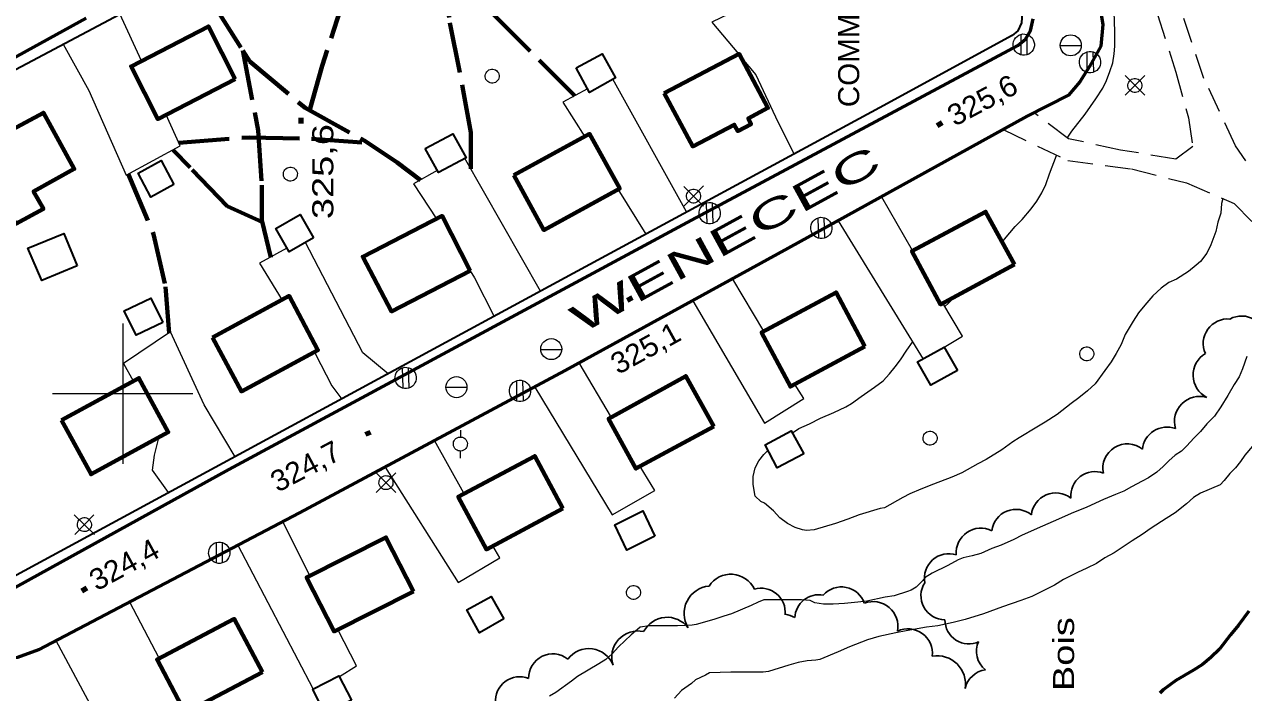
# Model space of a CAD drawing. Extents: x 240591 to 242335, y 5323482 to 5326937.
# Drawn here: x 241186 to 241359.7, y 5324557.4 to 5324652.6 of the extents above; entities that cross this region are included whole.
import ezdxf
from ezdxf.enums import TextEntityAlignment as Align

# ---------------------------------------------------------------- set-up
doc = ezdxf.new("R2010")
doc.units = 0
doc.header["$LTSCALE"] = 1.2
doc.linetypes.add('LONG_DASHED', pattern=[7.5, 6, -1.5])
doc.linetypes.add('MEDIUM_DASHED', pattern=[4.5, 3, -1.5])
for name, color, linetype, lineweight in [('1', 7, 'Continuous', 53), ('19', 7, 'Continuous', 13), ('2', 7, 'Continuous', 13), ('21', 7, 'Continuous', 53), ('22', 7, 'LONG_DASHED', 70), ('3', 7, 'Continuous', 140), ('31', 7, 'Continuous', 70), ('36', 7, 'Continuous', 13), ('44', 7, 'Continuous', 25), ('61', 7, 'Continuous', 13)]:
    doc.layers.add(name, color=color, linetype=linetype, lineweight=lineweight)

msp = doc.modelspace()

# ---------------------------------------------------------------- linework, layer by layer
at = {"layer": '1', "linetype": 'LONG_DASHED'}
msp.add_lwpolyline([(241360.4, 5324569), (241358.9, 5324567), (241357.8, 5324565.6), (241356.2, 5324563.6), (241355, 5324562.4), (241353.8, 5324561.4), (241352.5, 5324560.6), (241350, 5324559.1), (241348.2, 5324557.8), (241347.7, 5324557.3)], dxfattribs=at)
at = {"layer": '19'}
for p, q in [((241202.7, 5324647.4), (241199.6, 5324654.1)), ((241280.3, 5324625.9), (241269.8, 5324644.8)), ((241259.5, 5324614.6), (241248.7, 5324633.6)), ((241270.5, 5324629.1), (241274.5, 5324622.7)), ((241312.5, 5324620.4), (241308.1, 5324628)), ((241301.9, 5324624.6), (241314, 5324604.9)), ((241291.3, 5324608.9), (241286.9, 5324616.3)), ((241269.6, 5324596.6), (241265, 5324604.4)), ((241248.6, 5324585.8), (241244.4, 5324593.3)), ((241226.7, 5324574), (241222.8, 5324581.7)), ((241216.4, 5324578.4), (241227.1, 5324558)), ((241205.2, 5324562.3), (241201, 5324570.3))]:
    msp.add_line(p, q, dxfattribs=at)
at = {"layer": '19', "linetype": 'MEDIUM_DASHED'}
for points in [[(241392.5, 5324606.1), (241384.7, 5324607.7), (241378.2, 5324613), (241369.4, 5324621), (241363, 5324628.7), (241358.5, 5324635.3), (241354, 5324644.9), (241349.9, 5324657.2), (241346.1, 5324667.4), (241343.3, 5324672.7), (241341.3, 5324676.6)], [(241335.8, 5324674.5), (241340.6, 5324670.9), (241344.5, 5324664.1), (241347.4, 5324654), (241350, 5324645.8), (241351.8, 5324639.3), (241352.4, 5324635.2), (241350, 5324633.4), (241342.1, 5324634.7), (241334.7, 5324636.3), (241329.8, 5324640)], [(241325.4, 5324637.6), (241334.6, 5324633.2), (241343.7, 5324632), (241351.5, 5324630), (241358.3, 5324627.1), (241363.6, 5324621.6), (241368.5, 5324615.9), (241373.3, 5324610.3), (241377.7, 5324604.4), (241381.7, 5324599.7), (241386.5, 5324594.9)]]:
    msp.add_lwpolyline(points, dxfattribs=at)
at = {"layer": '19'}
for points in [[(241286.4, 5324654.1), (241283.9, 5324652.9), (241287.7, 5324648.4)], [(241191.5, 5324649.8), (241195.2, 5324643.2), (241200.5, 5324631.1), (241208.2, 5324635.3), (241206.2, 5324639.7)], [(241288.2, 5324647.8), (241290.2, 5324645.4), (241293.3, 5324638.7), (241295.6, 5324634.2)], [(241266.2, 5324643.4), (241262.7, 5324641.5), (241265.8, 5324636.6)], [(241244.8, 5324631.8), (241241.4, 5324629.9), (241244.7, 5324624.9)], [(241223.4, 5324620.7), (241219.5, 5324618.6), (241222.7, 5324613.3)], [(241237.8, 5324602.8), (241234.2, 5324605.8), (241226, 5324621.6)], [(241249.5, 5324617.5), (241250.1, 5324616.5), (241252.9, 5324611)], [(241281.2, 5324613.2), (241291.4, 5324595.8), (241297, 5324599.3), (241295.7, 5324601.4)], [(241317, 5324606.6), (241319.6, 5324608.2), (241316.8, 5324612.9)], [(241216, 5324591), (241211.6, 5324598.4), (241206.8, 5324608.8), (241200.1, 5324604.3), (241201.5, 5324601.8)], [(241227.3, 5324605.9), (241227.4, 5324605.7), (241229.8, 5324601.1), (241231.2, 5324599.2)], [(241258.7, 5324600.9), (241269.7, 5324582.7), (241275.8, 5324586.2), (241273.7, 5324589.6)], [(241205.1, 5324593.7), (241204.5, 5324591.2), (241204.2, 5324589.1), (241206.5, 5324585.9)], [(241237.4, 5324589.5), (241247.8, 5324573.1), (241253.7, 5324576.6), (241252.7, 5324578.3)], [(241230.9, 5324559.7), (241233.3, 5324561.2), (241230.7, 5324566.3)], [(241190.5, 5324564.8), (241202.3, 5324542.8), (241208.4, 5324546.8)]]:
    msp.add_lwpolyline(points, dxfattribs=at)
at = {"layer": '2'}
for points in [[(241337.1, 5324639.8), (241338.6, 5324642), (241339.6, 5324643.5), (241340.1, 5324644.6), (241340.6, 5324645.9), (241341, 5324647.1), (241341.2, 5324648.4), (241341.3, 5324649.5), (241341.3, 5324651.6), (241341.2, 5324654.4), (241341, 5324655.7), (241340.6, 5324658), (241340.1, 5324660.7), (241339.7, 5324662.3), (241339.3, 5324663.8), (241338.6, 5324666.3), (241338, 5324668.2), (241337.6, 5324670.1), (241337.3, 5324671.8), (241337.3, 5324673.4)], [(241334.5, 5324636.4), (241335.2, 5324637.4), (241337.1, 5324639.8)], [(241325.3, 5324621.6), (241325.6, 5324622), (241327.1, 5324623.8), (241328.1, 5324624.8), (241329.4, 5324626.3), (241330.2, 5324627.4), (241330.9, 5324628.6), (241331.5, 5324629.8), (241332, 5324631.3), (241333, 5324633.9)], [(241356.7, 5324627.8), (241356.5, 5324627.1), (241356.4, 5324625.7), (241356, 5324624.4), (241355.7, 5324623.1), (241355, 5324621.2), (241354.4, 5324620), (241353.5, 5324618.8), (241352.9, 5324618.3), (241351.8, 5324617.4), (241350.1, 5324616.3), (241349, 5324615.8), (241347.9, 5324615), (241346.7, 5324613.9), (241345.6, 5324612.6), (241344.7, 5324611.5), (241343.9, 5324610.3), (241342.8, 5324608.4), (241342.2, 5324607), (241341.5, 5324605.7), (241340.8, 5324604.5), (241339.9, 5324603.3), (241338.5, 5324601.4), (241337.4, 5324600.4), (241336.2, 5324599.4), (241335.1, 5324598.6), (241333.1, 5324597), (241331.4, 5324595.9), (241330.2, 5324595.2), (241327.7, 5324593.7), (241326.8, 5324593.1), (241325.2, 5324592), (241323, 5324590.6), (241321.8, 5324590), (241319.5, 5324588.7), (241318.1, 5324588.1), (241315.5, 5324587.1), (241313.7, 5324586.4), (241312.1, 5324585.7), (241311.1, 5324585.2), (241308.5, 5324583.7), (241307.9, 5324583.6), (241304.9, 5324582.7), (241303.3, 5324582.1), (241301.5, 5324581.5), (241298.5, 5324580.6), (241297.4, 5324580.5), (241296.8, 5324580.6), (241295.8, 5324580.9), (241294.7, 5324581.5), (241293.6, 5324582.3), (241292.7, 5324583.3), (241291.4, 5324584.4), (241290.9, 5324584.6), (241290.1, 5324585.4), (241290, 5324585.9), (241289.8, 5324587.1), (241289.8, 5324588.2), (241290.1, 5324589.4), (241290.6, 5324590.4), (241291.3, 5324591.3), (241291.9, 5324591.9)], [(241317.1, 5324612.4), (241317.6, 5324612.9), (241318.6, 5324613.9)], [(241374.6, 5324608.4), (241373.9, 5324607.5), (241373.1, 5324606.3), (241371.9, 5324604.4), (241371.3, 5324603.3), (241370.2, 5324601.3), (241368.8, 5324598.7), (241367.8, 5324597.5), (241367.3, 5324597.2), (241364.9, 5324595.7), (241362.5, 5324594), (241361.7, 5324593.3), (241360.9, 5324592.5), (241359.8, 5324591.2), (241359.2, 5324590.3), (241358.5, 5324589.4), (241357.7, 5324588.6), (241356.9, 5324587.6), (241356.3, 5324587)], [(241295.4, 5324594.4), (241296.3, 5324595), (241297.8, 5324595.7), (241299.4, 5324596.5), (241301.3, 5324597.3), (241303, 5324598.1), (241303.8, 5324598.6), (241305.2, 5324599.6), (241307.1, 5324600.9), (241308.3, 5324601.8), (241309.2, 5324602.8), (241310, 5324603.8), (241310.8, 5324604.8), (241311.7, 5324606.2), (241312.5, 5324607.3)], [(241360.1, 5324605.3), (241359.5, 5324603.5), (241359, 5324602.4), (241358.3, 5324601.3), (241357.4, 5324599.7), (241356.4, 5324598.1), (241355.5, 5324596.8), (241354.4, 5324595.7), (241353.5, 5324594.6), (241352.6, 5324593.7), (241351.5, 5324592.5), (241350.8, 5324591.8), (241349.9, 5324591.2), (241349, 5324590.4), (241348.2, 5324589.6), (241347.3, 5324588.8), (241346.1, 5324588), (241345.2, 5324587.5), (241343.7, 5324586.7), (241342.6, 5324586.1), (241341.4, 5324585.6), (241339.7, 5324584.9), (241337.3, 5324583.8), (241335.1, 5324582.9), (241333.3, 5324582.1)], [(241333.3, 5324582.1), (241331, 5324581.1), (241328.1, 5324579.8), (241326.9, 5324579.2), (241325.1, 5324578.4), (241323.8, 5324577.9), (241322.2, 5324577.2), (241321, 5324576.9), (241319.7, 5324576.6), (241319, 5324576.3), (241317.5, 5324575.5), (241315.3, 5324574.4), (241314.3, 5324573.8), (241313.9, 5324573.3), (241313, 5324572.4), (241312.3, 5324572), (241311.8, 5324571.8), (241309.9, 5324571.2), (241308.6, 5324571), (241306, 5324570.4), (241304.7, 5324570.3), (241302.8, 5324570.1), (241301.2, 5324570), (241299.8, 5324570), (241298.6, 5324570.2), (241297.9, 5324570.5), (241296.7, 5324570.6), (241295.4, 5324570.6), (241292.9, 5324570.6), (241291.3, 5324570.6), (241290.5, 5324570.3), (241289.5, 5324569.8), (241286.7, 5324568.6), (241285.6, 5324568.3), (241284.2, 5324567.8), (241281.7, 5324567.1), (241281.1, 5324567), (241279, 5324566.9), (241277.7, 5324566.9), (241275, 5324566.9), (241273.7, 5324566.7), (241273.3, 5324566.4), (241272.4, 5324565.6), (241270.6, 5324563.9), (241269.7, 5324562.9), (241268.8, 5324562.1), (241267.8, 5324561.5), (241266.3, 5324560.6), (241264.8, 5324559.7), (241263.9, 5324559), (241261.7, 5324557.4), (241260.8, 5324556.9)]]:
    msp.add_lwpolyline(points, dxfattribs=at)
at = {"layer": '2', "linetype": 'LONG_DASHED'}
msp.add_lwpolyline([(241356.3, 5324587), (241353.5, 5324585.8), (241352.5, 5324585.2), (241351.5, 5324584.3), (241349.9, 5324583), (241348.6, 5324582.2), (241346.5, 5324580.8), (241345.2, 5324579.9), (241343.8, 5324579), (241341.2, 5324577.3), (241339.9, 5324576.6), (241338.7, 5324575.8), (241337.3, 5324575.1), (241336, 5324574.5), (241334, 5324573.5), (241332.7, 5324572.7), (241331.1, 5324571.9), (241329.5, 5324571.1), (241327.9, 5324570.5), (241325.3, 5324569.6), (241322.6, 5324568.6), (241320, 5324567.8), (241318.3, 5324567.4), (241316.1, 5324566.9), (241314.5, 5324566.7), (241311.6, 5324566.2), (241310.1, 5324565.9), (241307.7, 5324565.4), (241306.1, 5324564.9), (241303.5, 5324563.9), (241301.9, 5324563.2), (241299.3, 5324562.1), (241298.7, 5324562), (241297.5, 5324561.9), (241296.2, 5324561.7), (241294.9, 5324561.3), (241292, 5324560.4), (241291.2, 5324560.3), (241289.7, 5324560.3), (241286.6, 5324560.3), (241283.6, 5324560.2), (241283, 5324559.9), (241281.6, 5324559.2), (241281, 5324558.7), (241279.6, 5324557.7), (241278.6, 5324556.6)], dxfattribs=at)
at = {"layer": '21'}
for points in [[(241366.5, 5324742.9), (241344.3, 5324739.4), (241329.4, 5324736.8), (241327.6, 5324735.9), (241325.9, 5324733.9), (241325.5, 5324731.6), (241325.7, 5324729.8), (241330.1, 5324705.5), (241335.7, 5324675.6), (241339.6, 5324652.6), (241339.3, 5324649.5), (241337.7, 5324646.6), (241336.3, 5324644.4), (241334.7, 5324642.5), (241328.8, 5324639.5), (241294.8, 5324620.7), (241263, 5324603.3), (241225.2, 5324583), (241188, 5324563.5), (241185, 5324562.4), (241181.9, 5324562.1)], [(241194.8, 5324653.5), (241151.2, 5324629.5)], [(241183.3, 5324571.6), (241215.1, 5324589.2), (241281, 5324624.7), (241327.5, 5324649.6), (241328.6, 5324650.5), (241329.3, 5324651.7), (241329.7, 5324653.4)]]:
    msp.add_lwpolyline(points, dxfattribs=at)
at = {"layer": '22', "linetype": 'Continuous', "lineweight": 35}
msp.add_lwpolyline([(241316.5, 5324726), (241314.9, 5324725.6), (241318.8, 5324704.4), (241328.1, 5324654.2), (241328, 5324652.8), (241327.5, 5324651.7), (241326.7, 5324651), (241307.8, 5324640.7), (241263, 5324616.5), (241214.3, 5324590.1), (241182.6, 5324572.9), (241166.3, 5324578), (241147.5, 5324612.7), (241152.2, 5324628.5), (241178.5, 5324642.9), (241201.9, 5324655.3), (241204.1, 5324657.2), (241205.6, 5324659.7), (241206.6, 5324662.3), (241207.1, 5324665.6), (241206.6, 5324669.7), (241199.5, 5324707.4), (241198.3, 5324707)], dxfattribs=at)
at = {"layer": '22'}
for points in [[(241264.4, 5324642.4), (241253, 5324653.8), (241246.3, 5324660.9), (241242.5, 5324666.9), (241240.6, 5324673), (241240.1, 5324676.1)], [(241236.2, 5324675.4), (241236.2, 5324675.4), (241233.9, 5324663.6), (241231.9, 5324657.5), (241228.4, 5324646.7), (241226.6, 5324640.3)], [(241209.3, 5324662.3), (241213, 5324655.4), (241217.1, 5324648.9), (241218.1, 5324647.3), (241226, 5324640.7), (241234.5, 5324636), (241239.1, 5324632.9), (241242.4, 5324630.4)], [(241245.6, 5324660.7), (241246.6, 5324652.8), (241248.5, 5324643.2), (241249.6, 5324637.2), (241249.6, 5324632)], [(241217.1, 5324648.9), (241219.3, 5324637.5), (241219.8, 5324629.7), (241219.8, 5324624.7), (241221.1, 5324619.4)], [(241208, 5324635.7), (241218, 5324636.5), (241226.9, 5324636.3), (241234.9, 5324635.7)], [(241219.9, 5324624.4), (241214.9, 5324626.7), (241209.6, 5324632.2), (241207.2, 5324634.7)], [(241200.8, 5324631.3), (241204.4, 5324622.7), (241206.1, 5324615.2), (241206.6, 5324608.6)]]:
    msp.add_lwpolyline(points, dxfattribs=at)
at = {"layer": '3'}
for p, q in [((241225.4, 5324638.5), (241225.4, 5324639.3)), ((241316, 5324638.2), (241316.7, 5324638.6)), ((241271.9, 5324613.3), (241272.6, 5324613.7)), ((241234.6, 5324594.2), (241235.3, 5324594.5)), ((241194.2, 5324571.9), (241194.9, 5324572.3))]:
    msp.add_line(p, q, dxfattribs=at)
at = {"layer": '31'}
for points in [[(241216, 5324644.8), (241205, 5324639.1), (241201.2, 5324646.6), (241212.2, 5324652.3)], [(241277.1, 5324642.8), (241287.8, 5324648.4), (241291.9, 5324640.7), (241289.1, 5324639.2), (241289.5, 5324638.4), (241287.6, 5324637.4), (241287.1, 5324638.3), (241281.2, 5324635.2)], [(241178.5, 5324634.3), (241181.2, 5324635.8), (241180.7, 5324636.7), (241182.5, 5324637.7), (241183, 5324636.9), (241188.7, 5324640), (241193.1, 5324632), (241187.3, 5324628.8), (241188.7, 5324626.3), (241184.8, 5324624.2), (241183.1, 5324627.3), (241182.5, 5324627)], [(241255.7, 5324631.1), (241266.5, 5324637), (241270.8, 5324629.2), (241260, 5324623.3)], [(241249.5, 5324617.5), (241238.3, 5324611.7), (241234.2, 5324619.5), (241245.5, 5324625.3)], [(241327, 5324618.4), (241316.5, 5324612.7), (241312.4, 5324620.3), (241322.9, 5324625.9)], [(241212.8, 5324608), (241223.7, 5324613.9), (241227.8, 5324606.2), (241216.9, 5324600.3)], [(241305.7, 5324606.7), (241295.1, 5324601), (241291, 5324608.7), (241301.6, 5324614.4)], [(241191.3, 5324596.2), (241202.3, 5324602.2), (241206.5, 5324594.5), (241195.5, 5324588.5)], [(241284.2, 5324595.3), (241273.1, 5324589.3), (241269.2, 5324596.4), (241280.2, 5324602.5)], [(241262.7, 5324583.6), (241251.8, 5324577.8), (241247.8, 5324585.3), (241258.7, 5324591.1)], [(241241.4, 5324571.8), (241230.1, 5324566.1), (241226.2, 5324573.8), (241237.5, 5324579.5)], [(241219.9, 5324560.3), (241208.9, 5324554.5), (241204.9, 5324562.1), (241215.9, 5324567.9)]]:
    msp.add_lwpolyline(points, close=True, dxfattribs=at)
at = {"layer": '31', "lineweight": 35}
for points in [[(241264.6, 5324646.4), (241268.3, 5324648.4), (241270.2, 5324645), (241266.5, 5324642.9)], [(241243.1, 5324634.9), (241247, 5324637), (241248.9, 5324633.6), (241245, 5324631.5)], [(241207.3, 5324629.8), (241204, 5324628), (241202.2, 5324631.4), (241205.5, 5324633.2)], [(241227.2, 5324622.2), (241223.7, 5324620.2), (241221.8, 5324623.5), (241225.3, 5324625.5)], [(241193.5, 5324618.2), (241188.5, 5324616.1), (241186.5, 5324620.7), (241191.6, 5324622.8)], [(241205.7, 5324610.1), (241201.9, 5324608.3), (241200.2, 5324611.8), (241204, 5324613.6)], [(241318.9, 5324603.3), (241315.1, 5324601.2), (241313.2, 5324604.5), (241317, 5324606.6)], [(241297, 5324591.4), (241293.2, 5324589.4), (241291.5, 5324592.7), (241295.2, 5324594.7)], [(241275.8, 5324579.7), (241271.8, 5324577.7), (241270.1, 5324581.3), (241274.1, 5324583.3)], [(241254.3, 5324567.9), (241250.8, 5324565.9), (241249, 5324569.2), (241252.5, 5324571.1)], [(241232.6, 5324556.3), (241228.8, 5324554.4), (241227.1, 5324557.9), (241230.8, 5324559.8)]]:
    msp.add_lwpolyline(points, close=True, dxfattribs=at)
at = {"layer": '36'}
for p, q in [((241327.9, 5324651.1), (241327.9, 5324648.3)), ((241328.8, 5324648.3), (241328.8, 5324651.2)), ((241333.5, 5324649.6), (241336.5, 5324649.6)), ((241337.3, 5324648.6), (241337.3, 5324645.8)), ((241338.3, 5324645.8), (241338.2, 5324648.7)), ((241345.6, 5324642.5), (241342.8, 5324645.3)), ((241345.6, 5324645.3), (241342.8, 5324642.5)), ((241282.7, 5324629.6), (241279.9, 5324626.7)), ((241282.7, 5324626.7), (241279.9, 5324629.5)), ((241283.1, 5324627.1), (241283.2, 5324624.2)), ((241284.1, 5324624.3), (241284, 5324627.2)), ((241299, 5324625), (241299.1, 5324622.1)), ((241300, 5324622.2), (241299.9, 5324625.1)), ((241259.5, 5324606.3), (241262.5, 5324606.3)), ((241239.8, 5324603.7), (241239.9, 5324600.8)), ((241240.8, 5324600.8), (241240.7, 5324603.7)), ((241256.1, 5324601.8), (241256.1, 5324598.9)), ((241257.1, 5324598.9), (241257, 5324601.8)), ((241246, 5324600.9), (241249, 5324600.9)), ((241248.1, 5324594.8), (241248.1, 5324593.8)), ((241248.1, 5324590.8), (241248.1, 5324591.8)), ((241238.9, 5324585.9), (241236.1, 5324588.7)), ((241238.9, 5324588.7), (241236.1, 5324585.9)), ((241196, 5324579.9), (241193.1, 5324582.7)), ((241195.9, 5324582.7), (241193.2, 5324579.9)), ((241213.3, 5324578.7), (241213.3, 5324575.9)), ((241214.2, 5324575.9), (241214.2, 5324578.8))]:
    msp.add_line(p, q, dxfattribs=at)
for centre in [(241335.029, 5324649.612), (241261.039, 5324606.332), (241247.539, 5324600.912)]:
    msp.add_circle(centre, 1.5, dxfattribs=at)
for centre, major_axis in [((241328.335, 5324649.717), (-0.703, 1.345)), ((241337.775, 5324647.217), (-0.703, 1.345)), ((241252.63, 5324645.223), (-0.463, 0.886)), ((241344.162, 5324643.895), (-0.463, 0.886)), ((241223.88, 5324631.263), (-0.463, 0.886)), ((241281.302, 5324628.135), (-0.463, 0.886)), ((241283.605, 5324625.697), (-0.703, 1.345)), ((241299.505, 5324623.597), (-0.703, 1.345)), ((241337.31, 5324605.653), (-0.463, 0.886)), ((241240.295, 5324602.227), (-0.703, 1.345)), ((241256.585, 5324600.377), (-0.703, 1.345)), ((241314.99, 5324593.643), (-0.463, 0.886)), ((241248.092, 5324592.809), (-0.463, 0.886)), ((241237.502, 5324587.305), (-0.463, 0.886)), ((241194.542, 5324581.325), (-0.463, 0.886)), ((241213.755, 5324577.317), (-0.703, 1.345)), ((241272.76, 5324571.663), (-0.463, 0.886))]:
    msp.add_ellipse(centre, major_axis=major_axis, ratio=0.999959, dxfattribs=at)
at = {"layer": '44'}
for centre, radius, start, end in [((241283.87, 5324568.667), 3.918, 95.12637, 211.17952), ((241277.534, 5324564.38), 3.742, 37.11947, 152.98565), ((241273.363, 5324562.475), 3.701, 76.92219, 198.84014), ((241261.256, 5324559.48), 3.439, 51.44905, 181.38374), ((241266.381, 5324559.919), 3.735, 21.36031, 142.95107), ((241256.529, 5324556.208), 3.44, 67.9901, 184.63178)]:
    msp.add_arc(centre, radius, start, end, dxfattribs=at)
for centre, major_axis, ratio, start_param, end_param in [((241357.319, 5324607.201), (-2.419, -2.467), 0.983876, 3.8120188, 5.9298041), ((241359.359, 5324607.599), (2.95, 1.803), 0.996968, 5.6872704, 7.8072419), ((241356.039, 5324602.635), (-3.579, 0.102), 0.998923, 5.2771541, 7.4039113), ((241353.436, 5324595.963), (-2.625, 2.537), 0.99081, 5.2103775, 7.3242498), ((241348.69, 5324591.814), (-3.349, -0.872), 0.983157, 4.0916975, 5.9513048), ((241343.051, 5324589.392), (-2.907, -1.88), 0.988935, 3.4540905, 5.9199809), ((241338.463, 5324585.455), (-2.656, -2.208), 0.987836, 3.662851, 5.6845265), ((241332.904, 5324582.345), (-1.264, 3.264), 0.997523, 5.2548436, 7.3809155), ((241327.23, 5324580.016), (-1.292, 3.234), 0.998619, 5.2178864, 7.3464694), ((241322.217, 5324577.328), (-1.981, 2.889), 0.998952, 5.2187458, 7.3413298), ((241317.625, 5324573.747), (-2.57, -2.326), 0.986296, 3.6569167, 5.7463594), ((241286.623, 5324570.562), (0.803, 3.608), 0.999852, 5.3693893, 7.4984617), ((241290.931, 5324568.837), (2.42, 2.435), 0.998854, 5.3912488, 7.3499552), ((241299.171, 5324567.897), (-2.736, 2.087), 0.998231, 5.1828733, 6.8853508), ((241302.373, 5324569.011), (0.702, 3.372), 0.999864, 5.2485672, 7.3396215), ((241317.156, 5324571.195), (3.152, -1.427), 0.995436, 3.0002255, 5.1221097), ((241306.881, 5324566.825), (2.278, 2.706), 0.998822, 5.2194282, 7.3451972), ((241293.955, 5324565.133), (2.095, 2.734), 0.999643, 0.1084987, 0.5385547), ((241311.83, 5324562.977), (2.035, 2.856), 0.997861, 5.2195683, 7.339654), ((241320.56, 5324567.781), (-2.518, -2.377), 0.995937, 5.5337129, 7.5105903), ((241325.062, 5324563.269), (3.462, 0.109), 0.981892, 2.6806676, 3.9957655), ((241315.945, 5324558.541), (3.261, 2.51), 0.994814, 5.4875783, 7.3558637), ((241323.335, 5324557.237), (-2.763, -2.074), 0.991098, 4.2089227, 5.4134828)]:
    msp.add_ellipse(centre, major_axis=major_axis, ratio=ratio, start_param=start_param, end_param=end_param, dxfattribs=at)
at = {"layer": '61'}
for points in [[(241200, 5324610), (241200, 5324600), (241200, 5324590)], [(241190, 5324600), (241200, 5324600), (241210, 5324600)]]:
    msp.add_lwpolyline(points, dxfattribs=at)

# ---------------------------------------------------------------- texts
at = {"layer": '21', "width": 1.8}
msp.add_text('WENECEC', height=4, rotation=28.687, dxfattribs=at).set_placement((241265.2, 5324608.4))
at = {"layer": '3', "width": 1.05}
for s, rotation, p in [('325,6', 28.121, (241318.5, 5324638)), ('324,4', 28.683, (241196.3, 5324571.8))]:
    msp.add_text(s, height=3, rotation=rotation, dxfattribs=at).set_placement(p)
at = {"layer": '3'}
for s, rotation, width, p in [('325,6', 90, 1.35, (241230, 5324638.4)), ('324,7', 27.929, 1.05, (241231.395, 5324590.786))]:
    msp.add_text(s, height=3, rotation=rotation, dxfattribs=dict(at, width=width)).set_placement(p, align=Align.RIGHT)
at = {"layer": '3', "width": 1.05}
msp.add_text('325,1', height=3, rotation=28.863, dxfattribs=at).set_placement((241275.176, 5324605.177), align=Align.CENTER)
at = {"layer": '31', "width": 1.05}
msp.add_text('COMMUNAUTAIRE', height=3, rotation=90, dxfattribs=at).set_placement((241304.9, 5324640.8))
at = {"layer": '44', "width": 1.35}
msp.add_text('Bois', height=3, rotation=90, dxfattribs=at).set_placement((241335.5, 5324557.6))

doc.saveas('drawing.dxf')
